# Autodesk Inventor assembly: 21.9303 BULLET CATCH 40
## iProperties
Created: 2012-06
Part Number: 21.9303 BULLET CATCH 40
Document SubType Name: Assembly
Designer: Administrator
Author: Administrator
